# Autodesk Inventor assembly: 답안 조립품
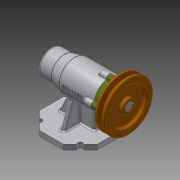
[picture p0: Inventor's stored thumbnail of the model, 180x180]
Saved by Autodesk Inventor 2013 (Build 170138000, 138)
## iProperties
Created: 2019-12
Part Number: 답안 조립품
Document SubType Name: Assembly
Designer: Administrator
Author: Administrator
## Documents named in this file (12)
- C:\Users\Administrator\Documents\Inventor\491204V1028\답안 조립품.iam
- C:\Users\Administrator\Documents\Inventor\491204V1028\본체.ipt
- C:\Users\Administrator\Documents\Inventor\491204V1028\491204V1028\V벨트풀리.ipt
- C:\Users\Administrator\Documents\Inventor\491204V1028\491204V1028\멈춤나사 M3.ipt
- C:\Users\Administrator\Documents\Inventor\491204V1028\491204V1028\베어링 6004.ipt
- C:\Users\Administrator\Documents\Inventor\491204V1028\491204V1028\베어링 51202.ipt
- C:\Users\Administrator\Documents\Inventor\491204V1028\491204V1028\볼트 M4.ipt
- C:\Users\Administrator\Documents\Inventor\491204V1028\491204V1028\어댑터슬리브.ipt
- C:\Users\Administrator\Documents\Inventor\491204V1028\491204V1028\오일 실.ipt
- C:\Users\Administrator\Documents\Inventor\491204V1028\491204V1028\축.ipt
- C:\Users\Administrator\Documents\Inventor\491204V1028\491204V1028\커버.ipt
- C:\Users\Administrator\Documents\Inventor\491204V1028\491204V1028\키 5 x 5 x 16.ipt
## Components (1 placed, 1 different names)
1. V벨트풀리:1
